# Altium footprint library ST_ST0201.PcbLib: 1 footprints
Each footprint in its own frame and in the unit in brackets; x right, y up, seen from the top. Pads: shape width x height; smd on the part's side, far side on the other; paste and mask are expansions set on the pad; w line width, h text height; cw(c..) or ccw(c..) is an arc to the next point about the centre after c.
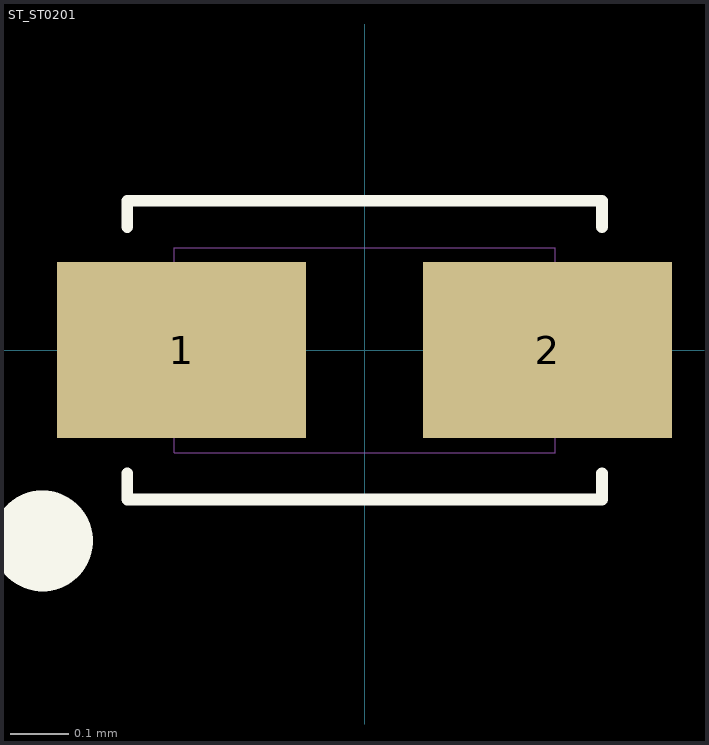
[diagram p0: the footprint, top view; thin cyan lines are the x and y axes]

## ST_ST0201 [mm] "ST_ST0201"
pads (2):
  rect 0.425x0.3 smd paste-20 mask+0.025: 1(-0.313,0) 2(0.312,0)
Top Overlay:
  circle w0.15: c-0.55,-0.326 r0.011
  lines w0.02: -0.405,-0.21 -0.405,-0.255 0.405,-0.255 0.405,-0.21 ; -0.405,0.21 -0.405,0.255 0.405,0.255 0.405,0.21
Top Paste:
  rectangle: -0.485,-0.112 -0.165,0.112
  rectangle: 0.165,-0.112 0.485,0.112
Mechanical 5:
  text "2" at 0.276,-0.468 h0.05
  text "1" at -0.297,-0.465 h0.05
Mechanical 6:
  lines w0: -0.325,-0.175 -0.325,0.175 0.325,0.175 0.325,-0.175 -0.325,-0.175
3D body: height 0.33, standoff 0, extent -0.325,-0.175 0.325,0.175
3D body: height 0.6, standoff 0, extent -0.325,0.175 -0.325,0.175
